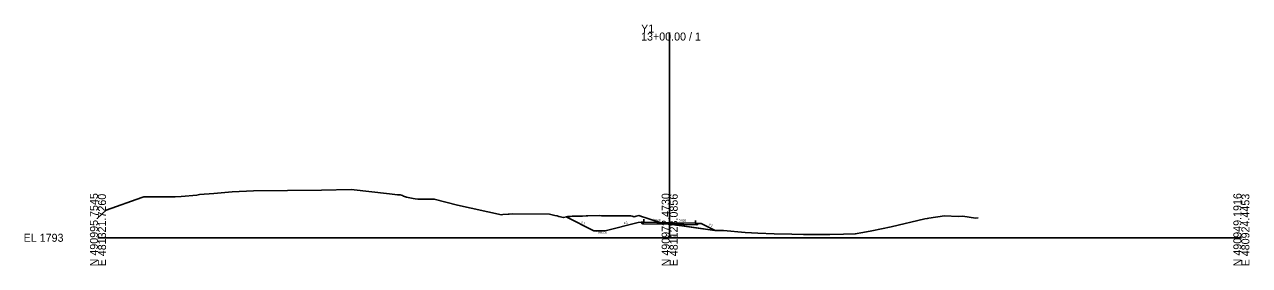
# Model space of a CAD drawing. Extents: x -26 to 403, y -10 to 6561.
# Drawn here: x -25.7 to 402.8, y 2990.3 to 3074.6 of the extents above; entities that cross this region are included whole.
import ezdxf

# ---------------------------------------------------------------- set-up
doc = ezdxf.new("R2010")
doc.units = 0
for name, color, linetype in [('Exist Cross Section Cell', 7, 'Continuous'), ('Exist XS Center Line Elevation Label', 7, 'Continuous'), ('Exist XS Ground Line', 7, 'Continuous'), ('Prop Road Sect_ Boring - Header (ID Tx)', 7, 'Continuous'), ('Prop Road Sect_ Material - Tx (Composite Desc)', 7, 'Continuous'), ('Prop XS Ditch Slope Text', 7, 'Continuous'), ('Prop XS Ditch Standard Text', 7, 'Continuous'), ('Prop XS EOT Tick Mark', 7, 'Continuous'), ('Prop XS Finish Grade', 7, 'Continuous'), ('Prop XS Finish Grade Earthwork', 7, 'Continuous'), ('Prop XS Finish Grade Pavement', 7, 'Continuous'), ('Prop XS Pvmt Edge Slope', 7, 'Continuous'), ('Prop XS SE Text', 7, 'Continuous'), ('Prop XS Side Slope Text', 7, 'Continuous'), ('Prop XS Subgrade Earthwork', 7, 'Continuous')]:
    doc.layers.add(name, color=color, linetype=linetype)

msp = doc.modelspace()

# ---------------------------------------------------------------- linework, layer by layer
at = {"layer": 'Exist Cross Section Cell'}
for p, q in [((200, 3000), (200, 3071.78)), ((0, 3000), (200, 3000)), ((200, 3000), (400, 3000))]:
    msp.add_line(p, q, dxfattribs=at)
at = {"layer": 'Exist XS Ground Line'}
msp.add_lwpolyline([(0, 3006.98), (2.9, 3009.69), (15.41, 3014.07), (16.06, 3014.26), (22.24, 3014.28), (26.49, 3014.28), (27, 3014.27), (29.1, 3014.47), (34.62, 3014.95), (35.54, 3015.11), (40.52, 3015.51), (47.01, 3016.08), (54.38, 3016.36), (78.25, 3016.67), (88.54, 3016.85), (102.05, 3015.34), (104.83, 3015.07), (105.73, 3015.02), (106.55, 3014.74), (106.86, 3014.52), (107.92, 3014.22), (110.31, 3013.79), (111.02, 3013.67), (111.95, 3013.53), (117.62, 3013.53), (125.83, 3011.42), (141.15, 3008.07), (141.69, 3008.11), (143.51, 3008.25), (143.83, 3008.28), (145.17, 3008.38), (157.94, 3008.28), (158.39, 3008.17), (159.87, 3007.8), (160.61, 3007.62), (161.2, 3007.48), (162.88, 3007.07), (163.96, 3007.35), (164.37, 3007.45), (164.87, 3007.48), (165.29, 3007.49), (165.88, 3007.52), (166.54, 3007.55), (167.6, 3007.57), (167.95, 3007.57), (169.47, 3007.6), (170.77, 3007.63), (171.39, 3007.64), (175.42, 3007.75), (176.21, 3007.73), (176.84, 3007.73), (177.64, 3007.71), (178.19, 3007.71), (179.08, 3007.69), (179.84, 3007.68), (180.5, 3007.67), (184.48, 3007.7), (185.04, 3007.68), (186.03, 3007.64), (186.43, 3007.63), (186.92, 3007.51), (187.58, 3007.35), (188.25, 3007.52), (189.2, 3007.76), (189.52, 3007.66), (190.53, 3007.33), (191.33, 3007.07), (191.68, 3006.95), (193.1, 3006.49), (194.78, 3005.95), (196.38, 3005.43), (196.81, 3005.29), (197.28, 3005.18), (200.06, 3004.78), (215.82, 3002.57), (216.77, 3002.55), (217.65, 3002.58), (218.85, 3002.51), (226.43, 3001.8), (230.85, 3001.64), (236.52, 3001.38), (242.75, 3001.31), (246.81, 3001.19), (248.02, 3001.17), (253.8, 3001.09), (256.03, 3001.09), (260.87, 3001.21), (264.95, 3001.37), (267.63, 3001.89), (270.67, 3002.45), (277.47, 3003.79), (289.31, 3006.6), (290.17, 3006.75), (290.7, 3006.82), (296.12, 3007.7), (300.95, 3007.47), (302.59, 3007.54), (306.95, 3006.9), (307.87, 3006.98)], dxfattribs=at)
at = {"layer": 'Prop Road Sect_ Boring - Header (ID Tx)'}
for points in [[(191, 3005.45), (190.47, 3004.92), (189.98, 3005.41)], [(209, 3005.09), (210.06, 3005.05), (209.55, 3004.54)]]:
    msp.add_lwpolyline(points, close=True, dxfattribs=at)
at = {"layer": 'Prop Road Sect_ Material - Tx (Composite Desc)'}
for points in [[(163.78, 3007.3), (163.96, 3007.35), (164.37, 3007.45), (164.87, 3007.48), (165.29, 3007.49), (165.88, 3007.52), (166.54, 3007.55), (167.6, 3007.57), (167.95, 3007.57), (169.47, 3007.6), (170.77, 3007.63), (171.39, 3007.64), (175.42, 3007.75), (176.21, 3007.73), (176.84, 3007.73), (177.64, 3007.71), (178.19, 3007.71), (179.08, 3007.69), (179.84, 3007.68), (180.5, 3007.67), (184.48, 3007.7), (185.04, 3007.68), (186.03, 3007.64), (186.43, 3007.63), (186.92, 3007.51), (187.58, 3007.35), (188.25, 3007.52), (189.2, 3007.76), (189.52, 3007.66), (190.53, 3007.33), (191.33, 3007.07), (191.68, 3006.95), (193.1, 3006.49), (194.78, 3005.95), (196.38, 3005.43), (196.81, 3005.29), (197.28, 3005.18), (200.06, 3004.78), (200.47, 3004.72), (199.98, 3004.73), (190.47, 3004.92), (189.98, 3005.41), (189, 3005.37), (177.42, 3002.48), (173.42, 3002.48)], [(200.47, 3004.72), (215.82, 3002.57), (215.89, 3002.57), (211, 3005.01), (210.06, 3005.05), (209.55, 3004.54)]]:
    msp.add_lwpolyline(points, close=True, dxfattribs=at)
at = {"layer": 'Prop XS EOT Tick Mark'}
for p, q in [((191, 3005.45), (191, 3006.45)), ((209, 3005.09), (209, 3006.09))]:
    msp.add_line(p, q, dxfattribs=at)
at = {"layer": 'Prop XS Finish Grade'}
for p, q in [((191, 3005.45), (189.98, 3005.41)), ((209, 3005.09), (210.06, 3005.05))]:
    msp.add_line(p, q, dxfattribs=at)
at = {"layer": 'Prop XS Finish Grade Earthwork'}
for p, q in [((173.42, 3002.48), (163.78, 3007.3)), ((189, 3005.37), (177.42, 3002.48)), ((189, 3005.37), (189.98, 3005.41)), ((210.06, 3005.05), (211, 3005.01)), ((211, 3005.01), (215.89, 3002.57)), ((177.42, 3002.48), (173.42, 3002.48))]:
    msp.add_line(p, q, dxfattribs=at)
at = {"layer": 'Prop XS Finish Grade Pavement'}
for p, q in [((191, 3005.45), (200, 3005.27)), ((200, 3005.27), (209, 3005.09))]:
    msp.add_line(p, q, dxfattribs=at)
at = {"layer": 'Prop XS Pvmt Edge Slope'}
for p, q in [((191, 3005.45), (190.47, 3004.92)), ((209, 3005.09), (209.55, 3004.54))]:
    msp.add_line(p, q, dxfattribs=at)
at = {"layer": 'Prop XS Subgrade Earthwork'}
for p, q in [((190.47, 3004.92), (189.98, 3005.41)), ((190.47, 3004.92), (199.98, 3004.73)), ((199.98, 3004.73), (209.55, 3004.54)), ((210.06, 3005.05), (209.55, 3004.54))]:
    msp.add_line(p, q, dxfattribs=at)

# ---------------------------------------------------------------- texts
at = {"layer": 'Exist Cross Section Cell'}
for s, p in [('Y1', (190, 3071.78)), ('13+00.00 / 1', (190, 3068.98)), ('EL 1793', (-26, 2998.6))]:
    msp.add_text(s, height=2.8, dxfattribs=at).set_placement(p)
for s, p in [('N 490995.7545', (0, 2990)), ('E 481321.7260', (2.8, 2990)), ('N 490972.4730', (200, 2990)), ('E 481123.0856', (202.8, 2990)), ('N 490949.1916', (400, 2990)), ('E 480924.4453', (402.8, 2990))]:
    msp.add_text(s, height=2.8, rotation=90, dxfattribs=at).set_placement(p)
at = {"layer": 'Exist XS Center Line Elevation Label'}
msp.add_text('1797.79', height=0.75, dxfattribs=at).set_placement((198.4, 3000.05))
at = {"layer": 'Prop XS Ditch Slope Text'}
msp.add_text('4:1', height=0.75, rotation=14.0362, dxfattribs=at).set_placement((184.04, 3004.68))
at = {"layer": 'Prop XS Ditch Standard Text'}
msp.add_text('1795.48', height=0.75, dxfattribs=at).set_placement((174.16, 3001.41))
at = {"layer": 'Prop XS SE Text'}
for p in [(194.17, 3005.89), (203.17, 3005.71)]:
    msp.add_text('0.020', height=0.75, rotation=358.8542, dxfattribs=at).set_placement(p)
at = {"layer": 'Prop XS Side Slope Text'}
for p in [(168.92, 3005.12), (213.57, 3004.4)]:
    msp.add_text('2:1', height=0.75, rotation=333.4349, dxfattribs=at).set_placement(p)

doc.saveas('drawing.dxf')
